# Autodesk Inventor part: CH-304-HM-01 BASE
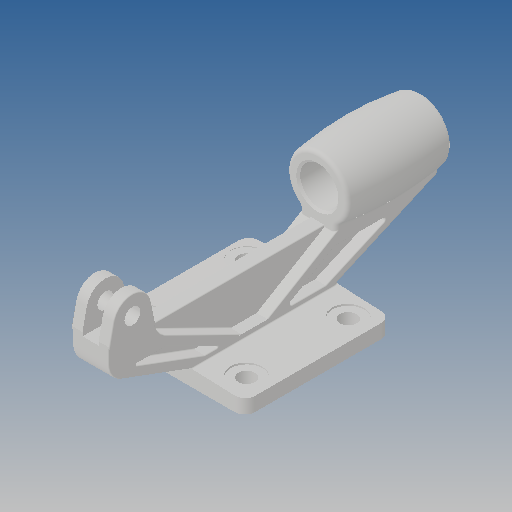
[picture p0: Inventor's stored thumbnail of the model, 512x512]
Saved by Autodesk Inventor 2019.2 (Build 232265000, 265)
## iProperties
Created: 2015-08
Part Number: CH-304-HM-01 BASE
Material: Ogólny
Document SubType Name: Modeling
Designer: CADENGINEERING4
Density: 1 g/cm^3
Appearance: Domyślna
Author: CADENGINEERING4
Revision Number: ÈÎºÎ
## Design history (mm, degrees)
feature "µ¹½Ç1"
node "Bryła1"
